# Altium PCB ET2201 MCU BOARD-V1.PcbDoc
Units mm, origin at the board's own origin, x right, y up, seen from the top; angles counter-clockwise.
Board outline 75 x 70 mm, 2 copper layers (Top Layer, Bottom Layer); 76 components, 40 nets, 249 pads, 34 vias.
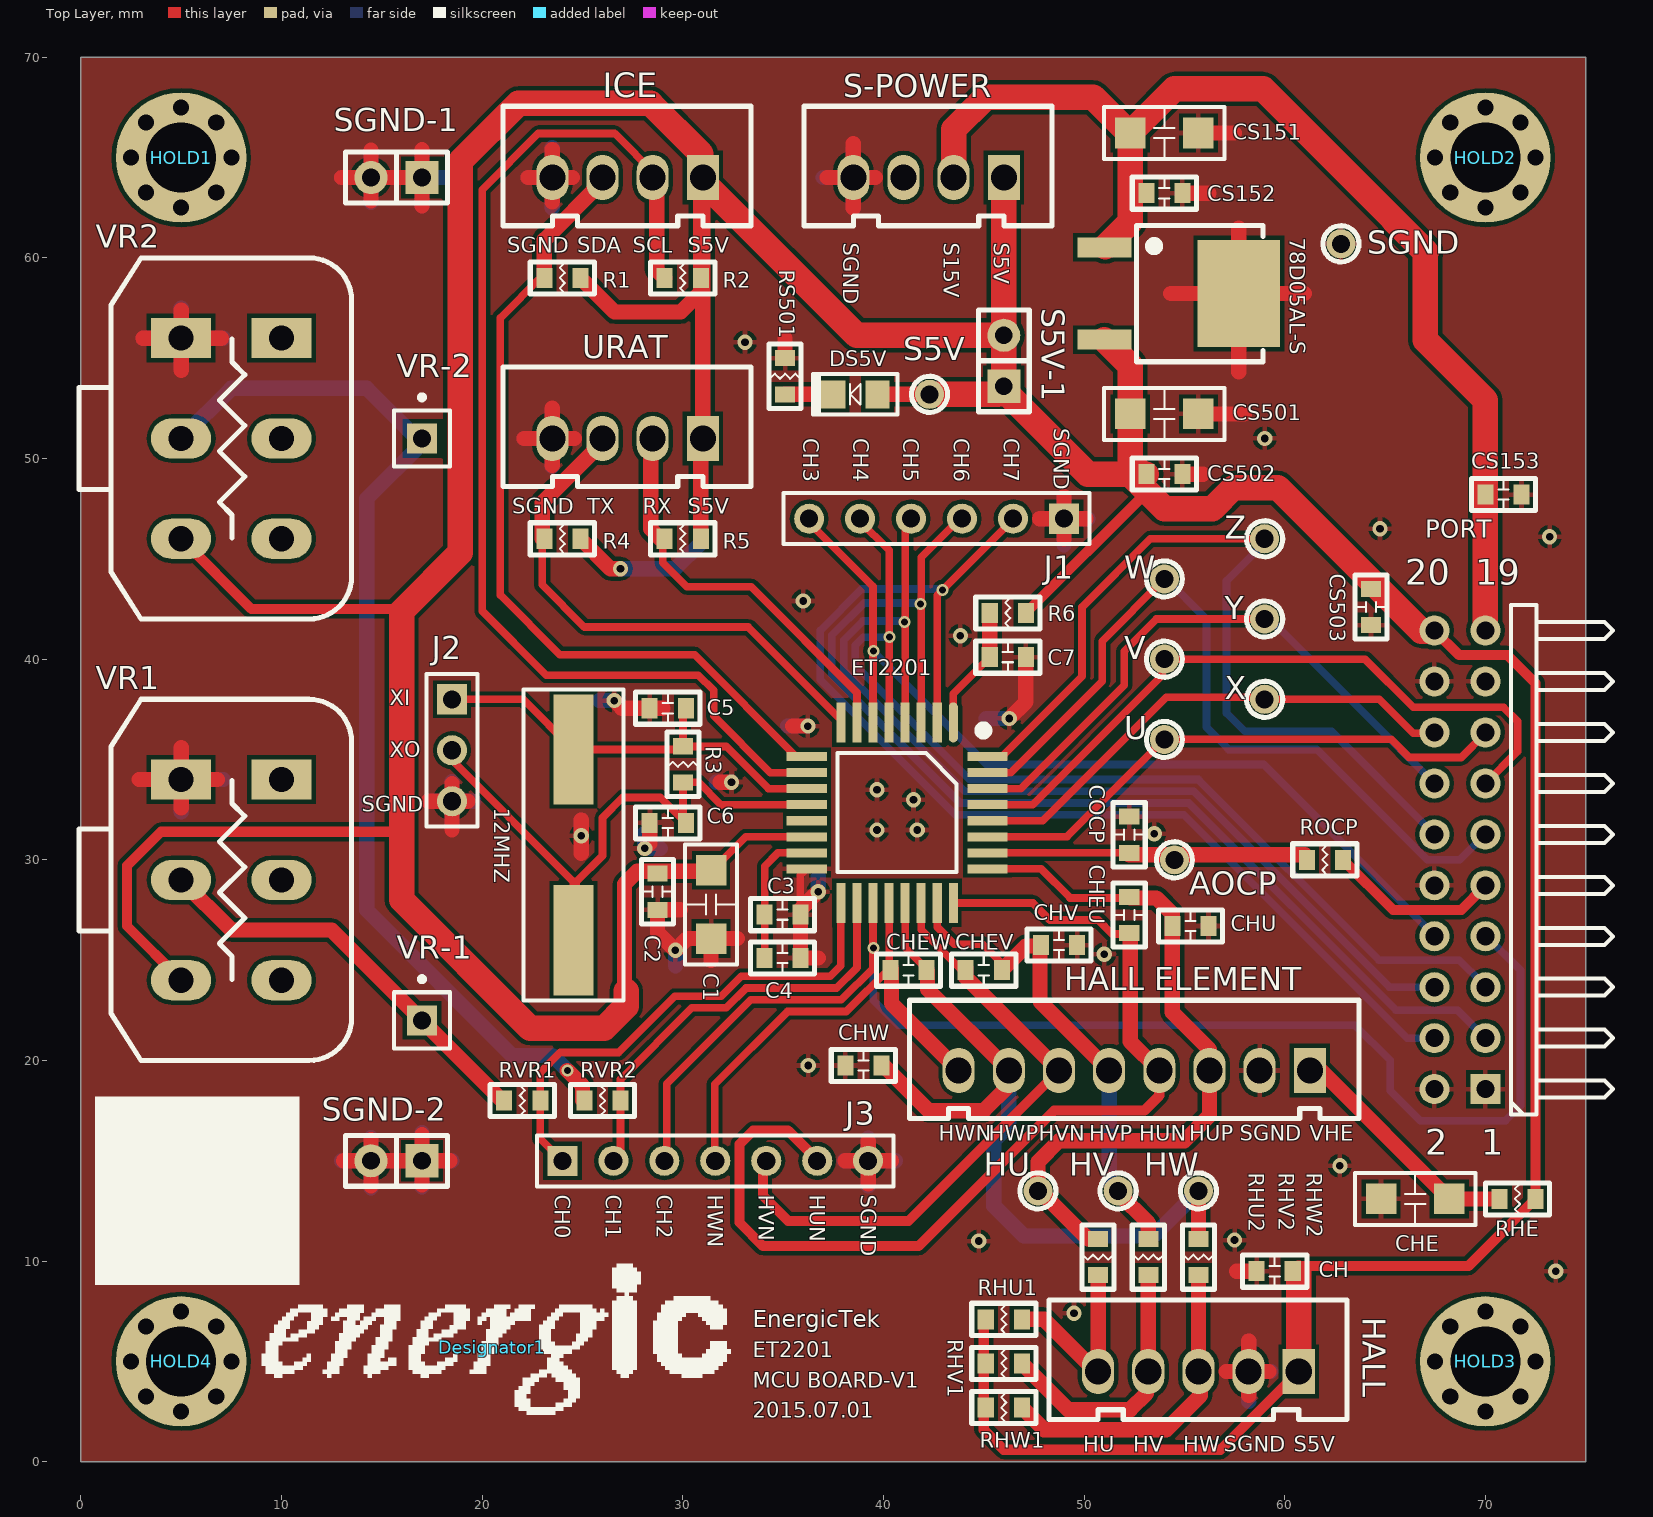
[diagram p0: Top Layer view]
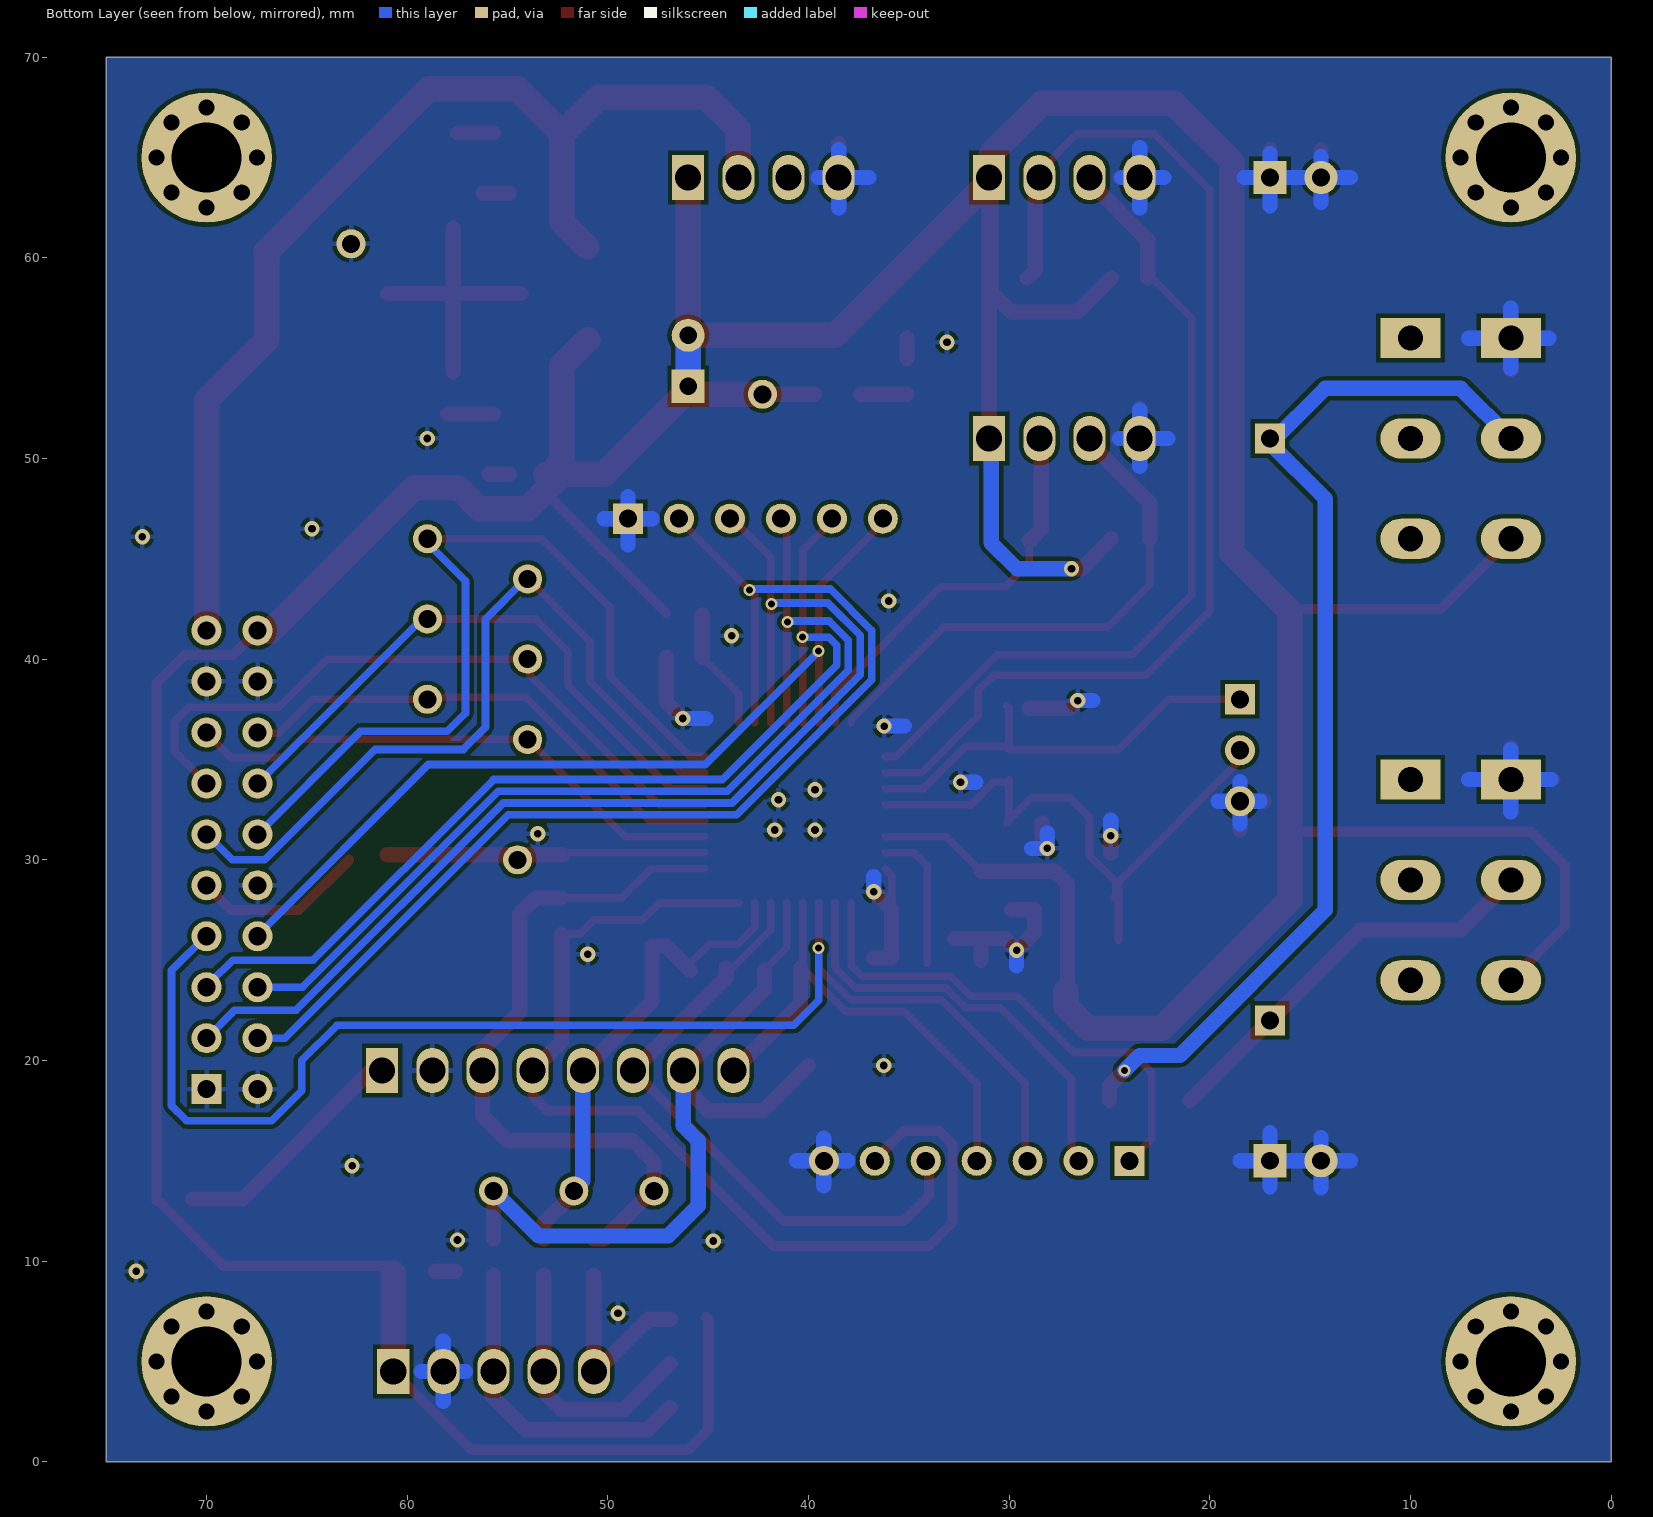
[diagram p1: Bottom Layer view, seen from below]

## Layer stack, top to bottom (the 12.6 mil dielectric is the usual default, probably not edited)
Top Layer: signal copper 0.0356
Dielectric: core 0.32, FR-4, Dk 4.8
Bottom Layer: signal copper 0.0356

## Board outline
0,0 0,70 75,70 75,0

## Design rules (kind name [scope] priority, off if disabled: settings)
Clearance [All] p1: gap=0.203
MinimumSolderMaskSliver [All] p1: minsoldermaskwidth=0.025
PolygonConnect [All] p1: connectstyle=Relief reliefconductorwidth=0.254 reliefentries=4 polygonreliefangle="90 Angle"
RoutingVias [All] p1: holewidth=0.127 width=0.254 viastyle="Through Hole" minholewidth=0.127 minwidth=0.254 maxholewidth=0.508 maxwidth=0.762
ShortCircuit ShortCircuit_1 [All] p1: allowed=FALSE
ShortCircuit [All] p2: allowed=FALSE
SilkToSilkClearance [All] p1: silktosilkclearance=0.076
SilkscreenOverComponentPads [All] p1: minsilkscreentomaskgap=0
SolderMaskExpansion [All] p1: expansion=0.102
Width [All] p1: maxlimit=1.27 minlimit=0.254 preferedwidth=0.508
24 further rules are at their usual default settings.

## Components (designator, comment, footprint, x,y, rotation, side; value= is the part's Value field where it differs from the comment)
12MHZ "12MHz" XTAL-SMD 24.553,25.997 r270 top
78D05AL-S "UTC78D05AL/DPAK" IC-7805-DPAK 55,58.222 r270 top
AOCP "" TP-R-0.9mm 54.5,30 r90 top
C1 "10UF/25V/1206" C1206 31.411,27.775 r270 top
C2 "0.1UF/50V/0603" C0603 28.744,28.41 r90 top
C3 "1UF/16V/0603" C0603 34.967,27.267 r180 top
C4 "0.1UF/50V/0603" C0603 34.967,25.108 r180 top
C5 "22pF/25V/0603" C0603 29.252,37.554 r0 top
C6 "22PF/25V/0603" C0603 29.252,31.839 r0 top
C7 "1UF/16V/0603" C0603 46.2,40.1 r180 top
CH "1UF/16V/0603" C0603 59.5,9.5 r0 top
CHE "10UF/25V/1206" C1206 66.5,13.1 r180 top
CHEU "10nF/50V/0603" C0603 52.25,27.25 r270 top
CHEV "10nF/50V/0603" C0603 45,24.5 r180 top
CHEW "10nF/50V/0603" C0603 41.25,24.5 r180 top
CHU "1000PF/50V/0603" C0603 55.3,26.7 r0 top
CHV "1000PF/50V/0603" C0603 48.75,25.75 r0 top
CHW "1000PF/50V/0603" C0603 39,19.75 r180 top
COCP "1000PF/50V/0603" C0603 52.25,31.25 r90 top
CS151 "10UF/25V/1206" C1206 54,66.222 r0 top
CS152 "0.1UF/50V/0603" C0603 54,63.222 r0 top
CS153 "0.1UF/50V/0603" C0603 70.9,48.2 r180 top
CS501 "10UF/25V/1206" C1206 54,52.222 r0 top
CS502 "0.1UF/50V/0603" C0603 54,49.222 r0 top
CS503 "0.1UF/50V/0603" C0603 64.3,42.6 r90 top
Designator1 "Comment" energic 20.5,5.7 r0 top
DS5V "LED/0805" LED-0805 38.6,53.2 r180 top
ET2201 "ET2201-LQFP32" IC-LQFP7x7-32-ET 40.682,32.347 r270 top (schematic designator IC1)
HALL "" CON-5P-2.5 60.7,4.5 r180 top
"HALL ELEMENT" "CON8/2.5/180" CON-8P-2.5 52.5,19.5 r180 top
HOLD1 "TP" HOLD-3-6 5,65 r0 top
HOLD2 "TP" HOLD-3-6 70,65 r0 top
HOLD3 "TP" HOLD-3-6 70,5 r0 top
HOLD4 "TP" HOLD-3-6 5,5 r0 top
HU "" TP-R-0.9mm 47.7,13.5 r0 top
HV "" TP-R-0.9mm 51.7,13.5 r0 top
HW "" TP-R-0.9mm 55.7,13.5 r0 top
ICE "CON4/2.5/180" CON-4P-2.5 31,64 r180 top
J1 "CON6/2.5/180" HDR1X6 49,47 r180 top
J2 "CON3/2.5/180" HDR1X3 18.5,38 r270 top
J3 "CON5/2.5/180" HDR1X7 24,15 r0 top
PORT "CON20/2.5/90" HDR2X10H 70,18.57 r90 top locked
R1 "4.7K/0603" R0603 24,59 r0 top
R2 "4.7K/0603" R0603 30,59 r0 top
R3 "1M/0603" R0603 30.014,34.76 r270 top
R4 "4.7K/0603" R0603 24,46 r0 top
R5 "4.7K/0603" R0603 30,46 r0 top
R6 "10K/0603" R0603 46.2,42.3 r0 top
RHE "2K/0603" R0603 71.6,13.1 r0 top
RHU1 "4.7K/0603" R0603 46,7.1 r0 top
RHU2 "1K/0603" R0603 50.7,10.2 r90 top
RHV1 "4.7K/0603" R0603 46,4.9 r0 top
RHV2 "1K/0603" R0603 53.2,10.2 r90 top
RHW1 "4.7K/0603" R0603 46,2.7 r0 top
RHW2 "1K/0603" R0603 55.7,10.2 r90 top
ROCP "2.2K/0603" R0603 62,30 r0 top
RS501 "4.7K/0603" R0603 35.1,54.1 r270 top
RVR1 "0R/0603" R0603 22,18 r180 top
RVR2 "0R/0603" R0603 26,18 r180 top
S5V "" TP-R-0.9mm 42.3,53.2 r0 top
S5V-1 "Header 2" CON-SIP2 46,53.6 r90 top
S-POWER "CON4/2.5/180" CON-4P-2.5 46,64 r180 top
SGND "" TP-R-0.9mm 62.8,60.7 r90 top
SGND-1 "Header 2" CON-SIP2 17,64 r180 top
SGND-2 "Header 2" CON-SIP2 17,15 r180 top
U "" TP-R-0.9mm 54,36 r90 top
URAT "CON4/2.5/180" CON-4P-2.5 31,51 r180 top
V "" TP-R-0.9mm 54,40 r90 top
VR1 "10K/VR/DIP" VR-6P-5.0 5,29 r90 top
VR2 "10K/VR/DIP" VR-6P-5.0 5,51 r90 top
VR-1 "Plug" PIN1 17,22 r0 top
VR-2 "Plug" PIN1 17,51 r0 top
W "" TP-R-0.9mm 54,44 r90 top
X "" TP-R-0.9mm 59,38 r90 top
Y "" TP-R-0.9mm 59,42 r90 top
Z "" TP-R-0.9mm 59,46 r90 top

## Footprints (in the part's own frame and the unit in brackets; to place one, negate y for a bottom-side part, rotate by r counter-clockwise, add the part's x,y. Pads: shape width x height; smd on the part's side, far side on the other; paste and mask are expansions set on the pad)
C0603 [mm]
  rect 0.8x1 smd: 1(-0.9,0) 2(0.9,0)
  silkscreen extent -1.6,-0.8 1.6,0.8
C1206 [mil]
  rect 60x60 smd: 1(66.93,0) 2(-66.93,0)
  silkscreen extent -118,-51 118,51
CON-4P-2.5 [mm]
  rect 1.6x2.25 hole 1.3: 1(0,0)
  oval 1.6x2.25 hole 1.3: 2(2.5,0) 3(5,0) 4(7.5,0)
  silkscreen extent -2.4,-3.56 9.95,2.4
CON-5P-2.5 [mm]
  rect 1.6x2.25 hole 1.3: 1(0,0)
  oval 1.6x2.25 hole 1.3: 2(2.5,0) 3(5,0) 4(7.5,0) 5(10,0)
  silkscreen extent -2.4,-3.56 12.45,2.4
CON-8P-2.5 [mm]
  rect 1.6x2.25 hole 1.3: 1(-8.75,0)
  oval 1.6x2.25 hole 1.3: 2(-6.25,0) 3(-3.75,0) 4(-1.25,0) 5(1.25,0) 6(3.75,0) 7(6.25,0) 8(8.75,0)
  silkscreen extent -11.2,-3.5 11.2,2.4
CON-SIP2 [mil]
  rect 65x65 hole 35: 1(0,0)
  round 65 hole 35: 2(100,0)
  silkscreen extent -50,-50 150,50
energic [mm]
  silkscreen extent -11.48,-3.35 11.89,4.17
HDR1X3 [mm] "Connector; Header; 3 Position"
  rect 1.5x1.5 hole 0.9: 1(0,0)
  round 1.5 hole 0.9: 2(2.54,0) 3(5.08,0)
  silkscreen extent -1.27,-1.27 6.35,1.27
HDR1X6 [mm] "Connector; Header; 6 Position"
  rect 1.5x1.5 hole 0.9: 1(0,0)
  round 1.5 hole 0.9: 2(2.54,0) 3(5.08,0) 4(7.62,0) 5(10.16,0) 6(12.7,0)
  silkscreen extent -1.27,-1.27 13.97,1.27
HDR1X7 [mm] "Connector; Header; 7 Position"
  rect 1.5x1.5 hole 0.9: 1(0,0)
  round 1.5 hole 0.9: 2(2.54,0) 3(5.08,0) 4(7.62,0) 5(10.16,0) 6(12.7,0) 7(15.24,0)
  silkscreen extent -1.27,-1.27 16.51,1.27
HDR2X10H [mm] "Connector; Header; 10x2 Position; Right Angle"
  rect 1.5x1.5 hole 0.9: 1(0,0)
  round 1.5 hole 0.9: 2(0,2.54) 3(2.54,0) 4(2.54,2.54) 5(5.08,0) 6(5.08,2.54) 7(7.62,0) 8(7.62,2.54) 9(10.16,0) 10(10.16,2.54) 11(12.7,0) 12(12.7,2.54) 13(15.24,0) 14(15.24,2.54) 15(17.78,0) 16(17.78,2.54) 17(20.32,0) 18(20.32,2.54) 19(22.86,0) 20(22.86,2.54)
  silkscreen extent -1.27,-6.35 24.13,-1.27
HOLD-3-6 [mm]
  round 1.2 hole 0.8: 1(-2.5,0) 1(-1.75,-1.75) 1(-1.75,1.75) 1(-0.004,2.5) 1(0,-2.5) 1(1.75,-1.75) 1(1.75,1.75) 1(2.5,0)
  round 6.5 hole 3.5: 1(0,0)
IC-7805-DPAK [mm]
  rect 1x2.7 smd: 1(-2.3,-3.985) 3(2.3,-3.985)
  rect 5.35x4.1 smd: 2(0,2.715)
  rect 4.5x1 on Top Paste: ""(0,2.715) ""(0,3.985) ""(0,1.445)
  silkscreen extent -3.4,-2.38 3.4,3.92
IC-LQFP7x7-32-ET [mm]
  oval 2x0.45 smd: 1(-4.5,2.8)
  rect 2x0.45 smd: 2(-4.5,2) 3(-4.5,1.2) 4(-4.5,0.4) 5(-4.5,-0.4) 6(-4.5,-1.2) 7(-4.5,-2) 8(-4.5,-2.8) 17(4.5,-2.8) 18(4.5,-2) 19(4.5,-1.2) 20(4.5,-0.4) 21(4.5,0.4) 22(4.5,1.2) 23(4.5,2) 24(4.5,2.8)
  rect 0.45x2 smd: 9(-2.8,-4.5) 10(-2,-4.5) 11(-1.2,-4.5) 12(-0.4,-4.5) 13(0.4,-4.5) 14(1.2,-4.5) 15(2,-4.5) 16(2.8,-4.5) 25(2.8,4.5) 26(2,4.5) 27(1.2,4.5) 28(0.4,4.5) 29(-0.4,4.5) 30(-1.2,4.5) 31(-2,4.5) 32(-2.8,4.5)
  silkscreen extent -4.3,-2.97 2.97,4.5
LED-0805 [mm]
  rect 1.2x1.4 smd: 1(-1.1,0) 2(1.1,0)
  silkscreen extent -2.1,-1 2.1,1
PIN1 [mm] "Connector; Plug"
  rect 1.5x1.5 hole 0.9: 1(0,0)
  silkscreen extent -1.4,-1.4 1.4,2.17
R0603 [mm]
  rect 0.8x1 smd: 1(-0.9,0) 2(0.9,0)
  silkscreen extent -1.6,-0.8 1.6,0.8
TP-R-0.9mm [mm]
  round 1.45 hole 0.9: 1(0,0)
  silkscreen extent -0.9,-0.9 0.9,0.9
VR-6P-5.0 [mm]
  rect 2x3 hole 1.25: 1(5,0) 4(5,-5)
  oval 2x3 hole 1.25: 2(0,0) 3(-5,0) 5(0,-5) 6(-5,-5)
  silkscreen extent -9,-8.5 9,5.08
XTAL-SMD [mm]
  rect 5.5x2 smd: 1(0,0) 2(-9.5,0)
  silkscreen extent -12.5,-2.5 3,2.5

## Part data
12MHZ: library part 12MHZ/HC-4, "HC-49S,12.000000MHz,+-30ppm,JXC,SMD,¥x¿³¹"
AOCP HU HV HW S5V SGND U V W X Y Z: library part "TEST POINT", "TEST POINT"
C3 CH CHU CHV CHW: library part 0.1UF/50V/0603
C5 C7: library part 18PF/25V/0603
C6: library part 18PF/25V/0603, "18pF,25V,∮5%,NPO,0603"
CHEU CHEV CHEW: library part 0.1UF/50V/0603, "0.1uF(104)(100n),50V,∮10%,X7R,0603,PSA"
COCP: "1000pF(102)(1n),50V,∮10%,X7R,0603,PSA"
DS5V: library part LED-LC170JRCT/0805, "LED RED, L-C170JRCT, SMD0805"
HALL: library part CON5, "Connector"
"HALL ELEMENT": library part "Header 8", "Header, 8-Pin"
HOLD1 HOLD2 HOLD3 HOLD4: library part CON1, "Connector"
ICE S-POWER URAT: library part CON4/P2., "Header 180«×,CX-W2501-04,Pitch:2.5mm,4Pin,©Ó"
J1: library part "Header 6", "Header, 6-Pin"
J2: library part "Header 3", "Header, 3-Pin"
J3: library part "Header 7", "Header, 7-Pin"
PORT: library part "Header 10X2H", "Header, 10-Pin, Dual row, Right Angle"
R1 R2 R4 R5: library part 5.1K/0603
R6: "10K,1%,0603,PSA"
RHE: library part 1M/0603
RHU1 RHU2 RHV1 RHV2 RHW1 RHW2: library part 330R/0603
ROCP RVR1 RVR2: library part 100R/06, "100R,1%,0603,PSA,¥@·"
S5V-1 SGND-1 SGND-2: "Header, 2-Pin"
VR1 VR2: library part 10K/3362W, "3362W,10K(103),∮10%,ミΑ,D"

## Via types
v1: diameter 0.762, hole 0.381, Top Layer to Bottom Layer, 27 vias
v2: diameter 0.6, hole 0.35, Top Layer to Bottom Layer, 7 vias

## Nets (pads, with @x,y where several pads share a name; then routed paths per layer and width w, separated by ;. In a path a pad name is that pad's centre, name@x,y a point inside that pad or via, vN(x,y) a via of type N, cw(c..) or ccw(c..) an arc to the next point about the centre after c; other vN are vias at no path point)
AOCP: AOCP.1 COCP.1 ET2201.26 ROCP.1 | length 15.7
  Top Layer w0.381: ET2201.26 COCP.1@52.153,30.347
  Top Layer w0.762: COCP.1@52.25,30.25 ROCP.1@61,30.25
AOCP_IN: PORT.9 ROCP.2 | length 8.6
  Top Layer w0.508: ROCP.2 65.4,27.5 68.8,27.5 PORT.9@70,28.7
CH0: ET2201.17 J3.1 RVR1.1 | length 25.2
  Top Layer w0.381: J3.1 22.9,16.1 22.9,19.4 23.9,20.4 26.8,20.4 29.603,23.203 31.918,23.203 32.908,24.194 37.355,24.194 37.882,24.721 ET2201.17
CH1: ET2201.18 J3.2 RVR2.1 | length 21.3
  Top Layer w0.381: J3.2@26.8,15.1 26.9,15.2 26.9,19.073 30.446,22.619 32.16,22.619 33.15,23.609 37.659,23.609 38.682,24.632 ET2201.18
CH2: ET2201.19 J3.3 PORT.7 | length 67.5
  Top Layer w0.381: J3.3@29.2,15 29.2,18.833 33.392,23.025 37.901,23.025 39.482,24.606 ET2201.19
  Bottom Layer w0.381: v2(39.5,25.6) 39.5,23 40.75,21.75 63.5,21.75 65.25,20 65.25,18.5 66.75,17 71,17 71.75,17.75 71.75,24.5 PORT.7@70,26.25
CH3: ET2201.6 J1.6 PORT.8 | length 45.3
  Top Layer w0.381: J1.6@36.2,46.9 39.482,43.618 ET2201.6
  Bottom Layer w0.381: v2(39.5,40.4) 45.15,34.75 58.95,34.75 PORT.8@67.5,26.2
CH4: ET2201.5 J1.5 PORT.5 | length 51.3
  Top Layer w0.381: J1.5@38.8,46.9 40.282,45.418 ET2201.5
  Bottom Layer w0.381: v2(40.3,41.1) 39,41.1 38.6,40.7 38.6,39.7 44.3,34 55.7,34 64.7,25 68.7,25 PORT.5@69.787,23.913
CH5: ET2201.4 J1.4 PORT.6 | length 51.1
  Top Layer w0.381: ET2201.4 41.082,46.682 J1.4@41.3,46.9
  Bottom Layer w0.381: v2@41.1,41.9 38.974,41.9 38.016,40.942 38.016,39.458 44.058,33.416 55.458,33.416 65.224,23.65 PORT.6
  other v2: 41.05,41.85
CH6: ET2201.3 J1.3 PORT.3 | length 57.9
  Top Layer w0.381: ET2201.3 41.882,45.082 J1.3@43.7,46.9
  Bottom Layer w0.381: v2@41.8,42.8 39.048,42.8 37.432,41.184 37.432,39.216 43.816,32.832 55.216,32.832 65.548,22.5 68.61,22.5 PORT.3
  other v2: 41.85,42.75
CH7: ET2201.2 J1.2 PORT.4 | length 59.2
  Top Layer w0.381: ET2201.2 42.682,43.182 v2(42.95,43.45) J1.2@46.5,47
  Bottom Layer w0.381: v2@43,43.5 38.921,43.5 36.847,41.426 36.847,38.974 43.574,32.247 54.974,32.247 66.111,21.11 PORT.4
HUN: "HALL ELEMENT.4" CHEU.2 ET2201.24 J3.6 | length 51.3
  Top Layer w0.381: ET2201.24 47.453,27.847 48.3,27 50.7,27 51.4,26.3 CHEU.2@52.2,26.3
  Top Layer w0.508: J3.6@36.75,15 35.25,16.5 33.5,16.5 32.827,15.827 32.827,11.923 34,10.75 41.75,10.75 48.5,17.5 53,17.5 53.75,18.25 53.75,19.5
  Top Layer w0.762: CHEU.2@52.3,26.3 52.3,20.95 53.75,19.5
HUP: "HALL ELEMENT.3" CHEU.1 CHU.1 ET2201.25 HU.1 RHU2.2 | length 36.6
  Top Layer w0.381: ET2201.25 47.853,29.547 49.3,28.1 CHEU.1@52.3,28.1
  Top Layer w0.762: HU.1 HU.1@47.7,13.6 ; RHU2.2 50.2,11.1 HU.1@47.7,13.6 ; CHEU.1@52.3,28.1 53.6,28.1 54.4,27.3 CHU.1 54.4,22.4 56.25,20.55 56.25,19.5 56.25,17.25 55,16 48.75,16 47.7,14.95 HU.1@47.7,13.6 ; 56.5,19.5 56.5,20.15
HVN: "HALL ELEMENT.6" CHEV.2 ET2201.22 J3.5 | length 31.9
  Top Layer w0.381: ET2201.22 41.882,26.518 CHEV.2@43.8,24.6 ; CHEV.2@44,24.4 CHEV.2@43.8,24.6 ; CHEV.2@44.2,24.6 44.1,24.6 CHEV.2@43.8,24.6
  Top Layer w0.508: J3.5@34,15 34,13.25 35.25,12 41.25,12 48.75,19.5
  Top Layer w0.762: CHEV.2@44.1,24.6 44.1,24.15 48.75,19.5
HVP: "HALL ELEMENT.5" CHEV.1 CHV.1 ET2201.23 HV.1 RHV2.2 | length 24
  Top Layer w0.381: ET2201.23 42.682,26.652 43.534,25.8 44.95,25.8 CHEV.1@46.075,24.675
  Top Layer w0.762: CHEV.1 46.075,24.675 47.1,25.7 47.8,25.7 47.8,22.95 51.25,19.5 51.25,19.65 ; HV.1@51.7,13.4 53.2,11.9 RHV2.2
  Bottom Layer w0.762: HV.1@51.25,14 51.25,19.5
HWN: "HALL ELEMENT.8" CHEW.2 ET2201.20 J3.4 | length 24.6
  Top Layer w0.381: J3.4@31.6,15 31.6,18.82 35.221,22.441 38.143,22.441 40.282,24.58 ET2201.20
  Top Layer w0.762: CHEW.2@40.4,24.6 40.4,22.85 43.75,19.5
HWP: "HALL ELEMENT.7" CHEW.1 CHW.1 ET2201.21 HW.1 RHW2.2 | length 40.2
  Top Layer w0.381: ET2201.21 41.082,25.618 42.2,24.5 CHEW.1@42.3,24.4
  Top Layer w0.762: CHW.1@40,19.75 42.25,17.5 45,17.5 46.25,18.75 46.25,19.5 42.2,23.55 CHEW.1@42.2,24.5 ; HW.1@55.5,13.3 55.7,13.1 RHW2.2
  Bottom Layer w0.762: 46.25,19.5 46.25,16.75 45.5,16 45.5,12.75 47,11.25 53.45,11.25 HW.1
NetCHE_2: "HALL ELEMENT.1" CHE.2 RHE.1 | length 11.4
  Top Layer w0.762: 61.8,19.5 CHE.2 ; CHE.2@68.4,13.1 RHE.1
NetDS5V_2: DS5V.2 RS501.2 | length 2.3
  Top Layer w0.762: RS501.2 DS5V.2@37.4,53.2
NetHALL_3: HALL.3 RHW1.2 RHW2.1 | length 15.8
  Top Layer w0.762: RHW1.2 48,1.6 54.1,1.6 55.8,3.3 HALL.3@55.8,4.3 ; HALL.3@55.7,4.6 RHW2.1
NetHALL_4: HALL.4 RHV1.2 RHV2.1 | length 13.3
  Top Layer w0.762: RHV1.2 49.2,2.6 52.3,2.6 53.1,3.4 HALL.4@53.1,4.4 ; HALL.4 RHV2.1
NetHALL_5: HALL.5 RHU1.2 RHU2.1 | length 9.6
  Top Layer w0.762: RHU1.2 48,7.1 HALL.5@50.6,4.5 ; HALL.5 RHU2.1
RSTN: C7.2 ET2201.1 R6.1 | length 6.1
  Top Layer w0.381: ET2201.1 43.482,38.282 C7.2
  Top Layer w0.762: C7.2 R6.1@45.3,42.2
RX: ET2201.7 R5.1 URAT.2 | length 20.2
  Top Layer w0.381: R5.1@29,45.9 29,44.8 30.2,43.6 33.417,43.6 38.682,38.335 ET2201.7
  Top Layer w0.762: URAT.2@28.4,50.9 28.4,46.5 R5.1@29,45.9
S15V: 78D05AL-S.1 CS151.2 CS152.1 CS153.2 PORT.19 S-POWER.2 | length 60.2
  Top Layer w1.27: S-POWER.2 43.5,66.4 45.1,68 50.458,68 CS151.2@52.3,66.158 ; 78D05AL-S.1@51.054,60.546 52.3,61.792 CS151.2@52.3,66.158 ; 65.4,61.9 67,60.3 67,55.9 70,52.9 70,51.5 PORT.19@70,41.5 ; 67.056,60.292 58.928,68.42 54.498,68.42 CS151.2 CS151.2@52.3,66.158
SCL-ICE: ET2201.10 ICE.2 R2.1 | length 57.3
  Top Layer w0.381: ICE.2@28.7,64.1 26.6,66.2 22.8,66.2 20,63.4 20,42.4 23.195,39.205 30.776,39.205 31.538,38.443 31.538,37.173 34.364,34.347 ET2201.10
  Top Layer w0.762: ICE.2@28.7,64.1 28.7,59.4 R2.1
SDA-ICE: ET2201.9 ICE.3 R1.1 | length 41.4
  Top Layer w0.381: R1.1@23,59.1 20.9,57 20.9,43.2 23.879,40.221 30.586,40.221 35.66,35.147 ET2201.9
  Top Layer w0.762: R1.1 23.1,60.9 ICE.3@26,63.8
TX: ET2201.8 R4.1 URAT.3 | length 26.1
  Top Layer w0.381: R4.1@23,46 23,43.7 25.1,41.6 33.268,41.6 37.882,36.986 ET2201.8
  Top Layer w0.762: R4.1@23,46 23,47.8 URAT.3@26,50.8
U: ET2201.27 PORT.15 U.1 | length 27.7
  Top Layer w0.381: ET2201.27 49.147,31.147 U.1 65.3,36 66.2,35.1 68.8,35.1 PORT.15@70,36.3
V: ET2201.29 PORT.13 V.1 | length 34.8
  Top Layer w0.381: ET2201.29 47.447,32.747 53.9,39.2 V.1@53.9,39.9 ; V.1@54.034,40.034 V.1 64,40 66.4,37.6 70.9,37.6 71.6,36.9 71.6,35.4 PORT.13@70,33.8
V25: C3.2 C4.2 ET2201.15 | length 7.2
  Top Layer w0.381: C4.2@34.078,24.854 34.078,29.68 34.745,30.347 ET2201.15
VDD5: 78D05AL-S.3 C1.2 C2.2 CH.2 CS501.2 CS502.1 CS503.2 DS5V.1 ET2201.14 HALL.1 ICE.1 PORT.20 R1.2 R2.2 R4.2 R5.2 R6.2 RHE.2 RHU1.1 RHV1.1 RHW1.1 S5V-1.1 S5V-1.2 S5V.1 S-POWER.1 URAT.1 VR1.3 VR2.3 | length 318.8
  Top Layer w0.381: C1.2@31.411,29.426 33.132,31.147 ET2201.14
  Top Layer w0.508: VR1.3 2.3,26.7 2.3,29.7 4,31.4 15.9,31.4 ; VR2.3 8.5,42.5 16.1,42.5 ; RHU1.1@45.1,7.2 45,7.1 45,1.6 46,0.6 56.8,0.6 HALL.1 ; R6.2 53.1,48.3 ; CH.2@60.75,9.75 69.15,9.75 RHE.2 ; PORT.20 68.69,40.2 71.1,40.2 72.5,38.8 RHE.2 ; RHE.2@72.5,13 RHE.2
  Top Layer w0.762: R4.2 26.4,44.5 v1(26.9,44.5) ; R1.2 26.6,57.3 29.9,57.3 30.9,58.3 R2.2 ICE.1@30.9,63.8 ; 27.093,23.457 27.093,28.791 27.728,29.426 C1.2@31.411,29.426 ; R5.2 URAT.1@30.9,51.2 ; URAT.1 31,63.8 ICE.1@31,63.9 ; DS5V.1 S5V.1 ; S5V-1.1@45.7,53.2 46,53.5 S5V-1.1
  Top Layer w1.27: 27.178,23.462 27.178,22.7 26.078,21.6 22.4,21.6 16,28 16,42.4 16.1,42.5 18.9,45.3 18.9,64.8 21.8,67.7 28.4,67.7 30.9,65.2 30.9,63.9 31,63.8 38.66,56.14 S5V-1.2 ; S5V.1 S5V-1.1@45.7,53.2 ; S5V-1.1@45.974,53.434 50.186,49.222 52.3,49.222 ; S5V-1.1 S5V-1.2 ; S-POWER.1@46,63.9 S5V-1.2 ; 50.44,49.222 52.3,49.222 ; 78D05AL-S.3 52.3,54.637 CS501.2 52.3,49.822 ; CS502.1 52.3,49.222 ; HALL.1 CH.2@60.7,9.4 ; PORT.20@67.4,41.4 66.8,41.4 59.65,48.55 57.45,48.55 56.4,47.5 54,47.5 52.3,49.2 52.3,49.222 ; 52.3,49.222 52.9,49.222 52.3,49.822 ; 52.3,49.222 52.3,49.822
  Bottom Layer w0.762: v1(26.9,44.5) 29.6,44.5 30.9,45.8 URAT.1@30.9,51
  Bottom Layer w1.27: S5V-1.1 S5V-1.2@46,56.1
VR1: RVR1.2 VR1.2 VR-1.1 | length 20.6
  Top Layer w0.762: VR1.2 7.5,26.5 12.5,26.5 VR-1.1 RVR1.2@21,18
VR2: RVR2.2 VR2.2 VR-2.1 | length 53.7
  Top Layer w0.762: v2(24.25,19.5) 25,18.75 RVR2.2@25,18
  Bottom Layer w0.762: VR2.2 7.5,53.5 14.25,53.5 17,50.75 14.25,48 14.25,27.5 21.5,20.25 23.5,20.25 v2(24.25,19.5)
VSS: 78D05AL-S.2 "HALL ELEMENT.2" C1.1 C2.1 C3.1 C4.1 C5.1 C6.1 C7.1 CH.1 CHE.1 CHU.2 CHV.2 CHW.2 COCP.2 CS151.1 CS152.2 CS153.1 CS501.1 CS502.2 CS503.1 ET2201.16 HALL.2 ICE.4 J1.1 J2.3 J3.7 PORT.1 PORT.2 PORT.10 PORT.17 PORT.18 RS501.1 S-POWER.4 SGND-1.1 SGND-1.2 SGND-2.1 SGND-2.2 SGND.1 URAT.4 VR1.1 VR2.1 | length 191.9
  Top Layer w0.381: C3.1@35.856,27.14 35.856,29.221 ET2201.16
  Top Layer w0.762: 2.9,34 VR1.1 ; 3.1,56 VR2.1 ; 5,32.6 VR1.1 ; 5,35.6 VR1.1 ; 5,54.4 VR2.1 ; 5,57.4 VR2.1 ; 6.8,34 VR1.1 ; 7,56 VR2.1 ; 13,64 SGND-1.2 ; 13.1,15 SGND-2.2 ; 14.46,13.76 SGND-2.2 ; 14.46,16.06 SGND-2.2 ; 14.46,62.84 SGND-1.2 ; 14.46,65.36 SGND-1.2 ; 17,13.8 SGND-2.1 ; 17,16.3 SGND-2.1 ; 17,62.6 SGND-1.1 ; 17,65.4 SGND-1.1 ; 17.299,32.92 J2.3 ; 18.4,15 SGND-2.1 ; 18.5,31.5 J2.3 ; 18.5,33.8 J2.3 ; 19.28,32.92 J2.3 ; 22.1,51 URAT.4 ; 22.3,64 ICE.4 ; 23.5,49.665 URAT.4 ; 23.5,52.5 URAT.4 ; 23.5,62.8 ICE.4 ; 23.5,65.4 ICE.4 ; 24.5,64 ICE.4 ; 24.6,51 URAT.4 ; 24.934,30.315 v1(24.934,31.204) 24.934,31.966 ; v1(26.585,37.935) 26.966,37.554 C5.1 28.998,37.554 ; v1(28.109,30.569) 28.352,30.812 C6.1 ; 29.876,27.51 C2.1 28.744,26.378 v1(29.633,25.489) 30.219,26.075 C1.1 ; 31.411,24.981 C1.1 ; 31.872,33.871 v1(32.427,33.871) ; 32.73,26.075 C1.1 ; RS501.1 35.1,56 ; 35.475,36.665 v1(36.237,36.665) ; C4.1@35.856,25.235 35.867,25.246 C3.1 35.867,27.532 v1(36.745,28.41) ; C4.1 36.745,25.108 ; 37.2,64 S-POWER.4 ; 38.1,15 J3.7 ; 38.5,62.5 S-POWER.4 ; 38.5,65.7 S-POWER.4 ; 39.24,13.84 J3.7 ; 39.24,15.96 J3.7 ; 39.6,64 S-POWER.4 ; 40.4,15 J3.7 ; v1(46.27,37.046) 47.1,37.876 C7.1 ; 47.794,47 J1.1 ; 49,46 J1.1 ; 49,48.1 J1.1 ; 50.1,47 J1.1 ; 54.322,58.222 78D05AL-S.2 ; CS502.2 55.922,49.222 ; CS152.2 56.222,63.222 ; CS501.1 57.978,52.222 ; CS151.1 57.478,66.222 ; 57.084,4.5 HALL.2 ; 57.6,9.5 CH.1 ; 78D05AL-S.2@57.693,58.2 78D05AL-S.2 ; 57.715,54.315 78D05AL-S.2 ; 57.715,61.485 78D05AL-S.2 ; 58.2,3.3 HALL.2 ; 58.2,6 HALL.2 ; 59.2,4.5 HALL.2 ; 60.978,58.222 78D05AL-S.2 ; SGND-2.2 SGND-2.1 ; SGND-1.2 SGND-1.1
  Bottom Layer w0.762: 3,34 VR1.1 ; 3.1,56 VR2.1 ; 5,32.4 VR1.1 ; 5,35.5 VR1.1 ; 5,54.5 VR2.1 ; 5,57.5 VR2.1 ; 7.1,34 VR1.1 ; 7.1,56 VR2.1 ; 13,15 SGND-2.2 ; 13,64 SGND-1.2 ; 14.46,13.64 SGND-2.2 ; 14.46,16.16 SGND-2.2 ; 14.46,62.76 SGND-1.2 ; 14.46,65.04 SGND-1.2 ; 17,13.7 SGND-2.1 ; 17,16.4 SGND-2.1 ; 17,62.6 SGND-1.1 ; 17,65.2 SGND-1.1 ; 17.52,32.92 J2.3 ; 18.3,64 SGND-1.1 ; 18.5,15 SGND-2.1 ; 18.5,31.8 J2.3 ; 18.5,33.9 J2.3 ; 19.58,32.92 J2.3 ; 22.1,51 URAT.4 ; 22.3,64 ICE.4 ; 23.5,49.6 URAT.4 ; 23.5,52.4 URAT.4 ; 23.5,62.5 ICE.4 ; 23.5,65.5 ICE.4 ; 24.4,64 ICE.4 ; 24.5,51 URAT.4 ; v1(24.934,31.204) 24.934,31.966 ; 25.823,37.935 v1(26.585,37.935) ; 28.109,31.331 v1(28.109,30.569) 28.871,30.569 ; 29.633,24.727 v1(29.633,25.489) ; 31.665,33.871 v1(32.427,33.871) ; 35.221,36.665 v1(36.237,36.665) ; v1(36.745,28.41) 36.745,29.172 ; 37,64 S-POWER.4 ; 38.034,15 J3.7 ; 38.5,62.5 S-POWER.4 ; 38.5,65.4 S-POWER.4 ; 39.24,13.76 J3.7 ; 39.24,16.14 J3.7 ; 39.5,64 S-POWER.4 ; 40.6,15 J3.7 ; 45.127,37.046 v1(46.27,37.046) ; 47.8,47 J1.1 ; 49,45.7 J1.1 ; 49,48.1 J1.1 ; 50.2,47 J1.1 ; 57.1,4.5 HALL.2 ; 58.2,3 HALL.2 ; 58.2,6 HALL.2 ; 59.316,4.5 HALL.2 ; PORT.18@67.39,38.8 PORT.18@67.46,38.73 ; SGND-2.2 SGND-2.1 ; SGND-1.2 SGND-1.1
  other v1: 49.5,7.4 73.5,9.5 44.75,11 57.5,11.05 62.75,14.75 36.25,19.75 51,25.3 53.5,31.3 39.679,31.488 41.679,31.488 41.5,33 39.679,33.488 43.837,41.165 36,42.9 73.2,46.1 64.75,46.5 59,51 33.1,55.8
W: ET2201.31 PORT.11 W.1 | length 39.6
  Top Layer w0.381: ET2201.31 46.347,34.347 50.9,38.9 50.9,40.9 W.1 W.1@54.25,44
  Bottom Layer w0.381: W.1@54.1,44 56.1,42 56.1,36.6 57.2,35.5 61.6,35.5 67.1,30 68.73,30 PORT.11
X: ET2201.28 PORT.16 X.1 | length 25.3
  Top Layer w0.381: ET2201.28 47.947,31.947 54.1,38.1 X.1@58.9,38.1 ; X.1 64.7,38 66.4,36.3 PORT.16@67.3,36.3
XTALI: 12MHZ.2 C5.2 ET2201.11 J2.1 R3.1 | length 22.2
  Top Layer w0.381: J2.1@18,38 22.05,38 12MHZ.2 29.989,35.497 30.141,35.649 32.173,35.649 34.275,33.547 ET2201.11 ; R3.1 30.014,37.554 C5.2@30.141,37.681
XTALO: 12MHZ.1 C6.2 ET2201.12 J2.2 R3.2 | length 30.6
  Top Layer w0.381: J2.2@18,35.4 18.071,35.4 24.553,28.918 12MHZ.1@24.553,27.902 ; 12MHZ.1 12MHZ.1@24.553,27.902 ; 12MHZ.1@24.7,28.2 24.7,28.9 26,30.2 26,32.1 27.009,33.109 28.871,33.109 C6.2@30.014,31.966 ; 12MHZ.1@24.776,28.124 12MHZ.1@24.553,27.902 ; R3.2@30.014,33.998 R3.2@30.083,33.929 ; C6.2@30.141,31.839 C6.2@30.014,31.966 ; 31.919,32.728 31.9,32.747 ; ET2201.12 31.9,32.747 ; C6.2@30.014,31.966 R3.2 30.787,33.86 31.9,32.747
Y: ET2201.30 PORT.14 Y.1 | length 30
  Top Layer w0.381: ET2201.30 46.847,33.547 52,38.7 52,40.4 53.6,42 Y.1
  Bottom Layer w0.381: Y.1@59.1,41.9 59.37,41.9 PORT.14
Z: ET2201.32 PORT.12 Z.1 | length 42.6
  Top Layer w0.381: ET2201.32 45.897,35.147 49.9,39.15 49.9,42.6 53.3,46 Z.1
  Bottom Layer w0.381: Z.1@59.1,45.9 57.1,43.9 57.1,37.3 58,36.4 62.33,36.4 PORT.12
pads on no net: 78D05AL-S. ET2201.13 HOLD1.1 HOLD2.1 HOLD3.1 HOLD4.1 S-POWER.3 VR1.4 VR1.5 VR1.6 VR2.4 VR2.5 VR2.6

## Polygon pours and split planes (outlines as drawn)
VSS on Top Layer "Bottom Layer-No Net" (solid, remove dead copper, pour order 3): 0,0 75,0 75,70 0,70
VSS on Bottom Layer "Bottom Layer-No Net" (solid, remove dead copper, pour order 4): 0,0 75,0 75,70 0,70

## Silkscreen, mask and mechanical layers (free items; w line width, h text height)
Top Overlay:
  rectangle: 0.7,8.8 10.9,18.2
  text "SGND" at 38,60.75 h0.76 r270
  text "S15V" at 43,60.75 h0.76 r270
  text "S5V" at 45.5,60.75 h0.76 r270
  text "SGND" at 21.25,60.25 h0.76
  text "SDA" at 24.75,60.25 h0.76
  text "SCL" at 27.5,60.25 h0.76
  text "S5V" at 30.25,60.25 h0.76
  text "SGND" at 48.5,51.5 h0.76 r270
  text "CH3" at 36,51 h0.76 r270
  text "CH4" at 38.5,51 h0.76 r270
  text "CH5" at 41,51 h0.76 r270
  text "CH6" at 43.5,51 h0.76 r270
  text "CH7" at 46,51 h0.76 r270
  text "SGND" at 21.5,47.25 h0.76
  text "TX" at 25.25,47.25 h0.76
  text "RX" at 28,47.25 h0.76
  text "S5V" at 30.25,47.25 h0.76
  text "XI" at 15.4,37.7 h0.76
  text "XO" at 15.4,35.1 h0.76
  text "SGND" at 14,32.4 h0.76
  text "HWN" at 42.75,16 h0.76
  text "HWP" at 45.25,16 h0.76
  text "HVN" at 47.75,16 h0.76
  text "HVP" at 50.25,16 h0.76
  text "HUN" at 52.75,16 h0.76
  text "HUP" at 55.25,16 h0.76
  text "SGND" at 57.75,16 h0.76
  text "VHE" at 61.25,16 h0.76
  text "CH0" at 23.622,13.302 h0.76 r270
  text "CH1" at 26.162,13.302 h0.76 r270
  text "CH2" at 28.702,13.302 h0.76 r270
  text "HWN" at 31.242,13.302 h0.76 r270
  text "HVN" at 33.782,13.302 h0.76 r270
  text "HUN" at 36.322,13.302 h0.76 r270
  text "SGND" at 38.862,13.302 h0.76 r270
  text "EnergicTek" at 33.5,6.7 h0.84
  text "ET2201" at 33.5,5.2 h0.76
  text "MCU BOARD-V1" at 33.5,3.7 h0.76
  text "2015.07.01" at 33.5,2.2 h0.76
  text "HU" at 49.95,0.5 h0.76
  text "HV" at 52.45,0.5 h0.76
  text "HW" at 54.95,0.5 h0.76
  text "SGND" at 56.95,0.5 h0.76
  text "S5V" at 60.45,0.5 h0.76
Mechanical 1:
  the board outline again, w0.254
Drill Drawing:
  text ".Legend" at 80.3,1.5 h1.52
